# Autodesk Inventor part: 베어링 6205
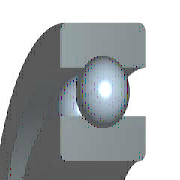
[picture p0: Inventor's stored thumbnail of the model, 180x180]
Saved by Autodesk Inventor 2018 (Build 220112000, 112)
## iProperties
Created: 2012-02
Part Number: 베어링 6205
Material: 강철, 연강
Description: 깊은 그루브 볼 베어링
Document SubType Name: Modeling
Standard: KS B 2023
Designer: mduedu
Standards Organization: KS
Language: ko-KR
Size Designation: 6205 - 25 x 52 x 15
Categories: <MemberInstance><Categories><Category DisplayName="샤프트 부품" InternalName="7f7aeb1f-a693-4053-b835-cee3144e0d98" Mnemonic="SHFT"><Category DisplayName="베어링" Inter
Density: 1 g/cm^3
Appearance: 노란색
IsCustomPart: 1
Author: mduedu
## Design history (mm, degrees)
sketch "스케치" dims "d0" = 7.02 (= -0.26 x WD + 0.26 x BD)
  geometry: L1 (3.99, 19.25)-(11.01, 19.25); L2 (7.5, 19.25)-(7.5, 15.74); L3 (7.5, 19.25)-(7.5, 22.76); L4 (4.892, 16.901)-(0, 16.901); L5 (0, 12.5)-(15, 12.5); L6 (4.892, 21.599)-(0, 21.599); L7 (0, 26)-(15, 26); L8 (15, 12.5)-(15, 16.901); L9 (10.108, 16.901)-(15, 16.901); L10 (10.108, 21.599)-(15, 21.599); L11 (15, 26)-(15, 21.599); L12 (-1.4, 0)-(8.4, 0) reference; L13 (0, -0.3)-(0, 5.3) reference
  constraints: 22 end point, 4 point on line, 2 collinear, 2 perpendicular, 2 symmetric about line, 1 midpoint, 1 parallel, 14 other
  dimensions: "d9" = 25 diameter of L5 L12 (= WD); "d11" = 52 diameter of L7 L12 (= BD); "d12" = 15 distance between parallel lines of L8 L13 (= KB); "d13" = 33.802 diameter of L9 L12 (= 0.326 x BD + 0.674 x WD)
revolve "본체" stored, may be unused: angle "d6" = 90 deg
revolve "볼" stored, may be unused: angle "d7" = 90 deg
pattern_circular "IDS_ARRAYBALL[SIMPL:T]" dims angle "d3" = 360 deg
body "Solid1"
fillet "모깎기1" dims "d1" = 1 (= KRS)
other parameters: "WD" = 25 [user parameter; used in 5 equation terms], "BD" = 52 [user parameter; used in 5 equation terms], "KB" = 15 [user parameter; used in 1 equation term], "KRS" = 1 [user parameter; used in 1 equation term], "d4" = 0, "d5" = 0, "d8" = 0, "d14" = 0, "d15" = 0, "BBA" = 0 [user parameter], "BC0" = 7800000 [user parameter], "BC" = 1.4e+07 [user parameter], "BR" = 26 (= 0.5 x BD) [user parameter], "WR" = 12.5 (= 0.5 x WD) [user parameter]
